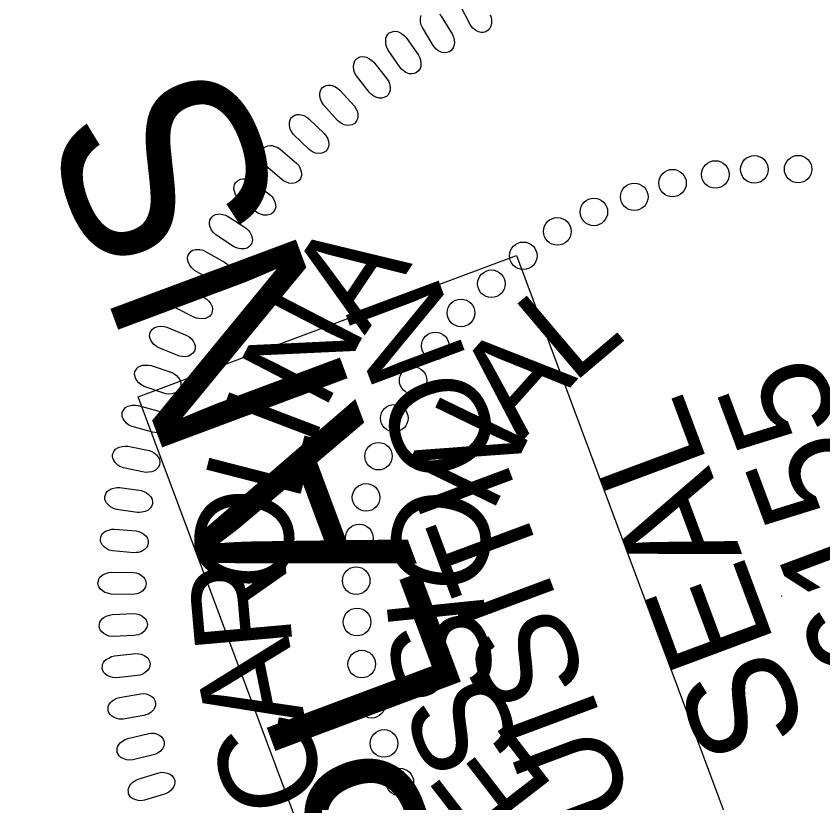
# Model space of a CAD drawing. Extents: x 477774 to 479389, y 493760 to 495720.
# Drawn here: x 477869.32 to 477916.27, y 495305.3 to 495351.06 of the extents above; entities that cross this region are included whole.
import ezdxf

# ---------------------------------------------------------------- set-up
doc = ezdxf.new("R2010")
doc.units = 0
for name, color, linetype in [('Sheet PE Seal Cell', 7, 'Continuous'), ('Sheet Plan CELL', 7, 'Continuous'), ('Sheet Sticker Incomplete CELL', 7, 'Continuous')]:
    doc.layers.add(name, color=color, linetype=linetype)

msp = doc.modelspace()

# ---------------------------------------------------------------- linework, layer by layer
at = {"layer": 'Sheet PE Seal Cell'}
msp.add_line((477913.867, 495317.32), (477913.91, 495317.336), dxfattribs=at)
for points in [[(477896.901, 495351.142), (477896.96, 495350.982), (477896.985, 495350.837), (477896.979, 495350.655), (477896.945, 495350.479), (477896.896, 495350.363), (477896.785, 495350.237), (477896.661, 495350.15), (477896.51, 495350.116), (477896.395, 495350.112), (477896.236, 495350.141), (477896.051, 495350.236), (477895.908, 495350.364), (477895.822, 495350.465), (477895.748, 495350.572), (477895.179, 495351.659)], [(477893.957, 495351.183), (477894.059, 495351.058), (477894.717, 495349.988), (477894.786, 495349.831), (477894.819, 495349.689), (477894.826, 495349.506), (477894.802, 495349.328), (477894.761, 495349.21), (477894.657, 495349.076), (477894.54, 495348.982), (477894.392, 495348.939), (477894.276, 495348.927), (477894.116, 495348.946), (477893.926, 495349.03), (477893.774, 495349.148), (477893.682, 495349.244), (477893.602, 495349.347), (477892.966, 495350.395), (477892.884, 495350.602), (477892.856, 495350.749), (477892.864, 495350.952), (477892.89, 495351.096)]]:
    msp.add_lwpolyline(points, dxfattribs=at)
for points in [[(477891.668, 495348.081), (477890.968, 495349.088), (477890.873, 495349.288), (477890.836, 495349.433), (477890.831, 495349.637), (477890.848, 495349.782), (477890.895, 495349.911), (477890.958, 495350.004), (477891.038, 495350.084), (477891.142, 495350.133), (477891.257, 495350.176), (477891.376, 495350.187), (477891.52, 495350.165), (477891.615, 495350.133), (477891.755, 495350.049), (477891.907, 495349.936), (477892.017, 495349.818), (477892.74, 495348.791), (477892.819, 495348.639), (477892.862, 495348.499), (477892.88, 495348.316), (477892.868, 495348.138), (477892.833, 495348.017), (477892.739, 495347.878), (477892.627, 495347.776), (477892.482, 495347.724), (477892.368, 495347.705), (477892.206, 495347.714), (477892.012, 495347.784), (477891.854, 495347.894), (477891.755, 495347.983)], [(477889.893, 495346.623), (477889.13, 495347.584), (477889.023, 495347.779), (477888.977, 495347.921), (477888.96, 495348.123), (477888.967, 495348.27), (477889.006, 495348.402), (477889.062, 495348.498), (477889.138, 495348.583), (477889.238, 495348.637), (477889.351, 495348.688), (477889.469, 495348.706), (477889.614, 495348.693), (477889.71, 495348.669), (477889.857, 495348.593), (477890.014, 495348.49), (477890.132, 495348.379), (477890.919, 495347.399), (477891.006, 495347.253), (477891.058, 495347.115), (477891.087, 495346.935), (477891.086, 495346.756), (477891.06, 495346.632), (477890.974, 495346.488), (477890.869, 495346.38), (477890.727, 495346.318), (477890.615, 495346.292), (477890.453, 495346.291), (477890.254, 495346.349), (477890.089, 495346.448), (477889.985, 495346.531)], [(477888.031, 495344.995), (477887.209, 495345.906), (477887.09, 495346.094), (477887.035, 495346.232), (477887.005, 495346.433), (477887.004, 495346.58), (477887.034, 495346.714), (477887.084, 495346.814), (477887.154, 495346.904), (477887.251, 495346.964), (477887.36, 495347.022), (477887.477, 495347.048), (477887.622, 495347.043), (477887.72, 495347.025), (477887.87, 495346.959), (477888.035, 495346.865), (477888.158, 495346.762), (477889.006, 495345.833), (477889.102, 495345.693), (477889.163, 495345.559), (477889.203, 495345.38), (477889.213, 495345.202), (477889.194, 495345.077), (477889.118, 495344.927), (477889.02, 495344.813), (477888.883, 495344.742), (477888.771, 495344.709), (477888.61, 495344.698), (477888.408, 495344.744), (477888.237, 495344.832), (477888.129, 495344.909)], [(477886.349, 495343.321), (477885.471, 495344.179), (477885.341, 495344.359), (477885.277, 495344.494), (477885.234, 495344.693), (477885.224, 495344.839), (477885.245, 495344.975), (477885.29, 495345.077), (477885.354, 495345.172), (477885.447, 495345.238), (477885.552, 495345.302), (477885.667, 495345.336), (477885.812, 495345.341), (477885.911, 495345.328), (477886.065, 495345.271), (477886.235, 495345.188), (477886.365, 495345.093), (477887.269, 495344.22), (477887.374, 495344.085), (477887.443, 495343.955), (477887.494, 495343.78), (477887.515, 495343.602), (477887.505, 495343.477), (477887.438, 495343.322), (477887.347, 495343.202), (477887.215, 495343.123), (477887.105, 495343.083), (477886.945, 495343.061), (477886.741, 495343.095), (477886.565, 495343.172), (477886.452, 495343.242)], [(477884.784, 495341.555), (477883.855, 495342.356), (477883.713, 495342.528), (477883.641, 495342.658), (477883.586, 495342.854), (477883.566, 495342.999), (477883.58, 495343.136), (477883.618, 495343.242), (477883.675, 495343.34), (477883.764, 495343.411), (477883.865, 495343.482), (477883.978, 495343.523), (477884.122, 495343.537), (477884.221, 495343.53), (477884.379, 495343.484), (477884.554, 495343.411), (477884.689, 495343.325), (477885.646, 495342.51), (477885.76, 495342.382), (477885.837, 495342.257), (477885.898, 495342.085), (477885.931, 495341.909), (477885.929, 495341.783), (477885.871, 495341.625), (477885.789, 495341.499), (477885.661, 495341.412), (477885.555, 495341.365), (477885.396, 495341.334), (477885.19, 495341.354), (477885.01, 495341.42), (477884.892, 495341.482)], [(477883.305, 495339.657), (477882.327, 495340.398), (477882.175, 495340.561), (477882.095, 495340.686), (477882.027, 495340.878), (477881.998, 495341.022), (477882.003, 495341.159), (477882.034, 495341.267), (477882.086, 495341.368), (477882.169, 495341.446), (477882.266, 495341.523), (477882.376, 495341.57), (477882.52, 495341.593), (477882.619, 495341.593), (477882.779, 495341.556), (477882.958, 495341.495), (477883.099, 495341.417), (477884.105, 495340.664), (477884.226, 495340.544), (477884.31, 495340.424), (477884.384, 495340.256), (477884.427, 495340.082), (477884.432, 495339.956), (477884.385, 495339.795), (477884.311, 495339.664), (477884.189, 495339.569), (477884.086, 495339.516), (477883.929, 495339.474), (477883.722, 495339.481), (477883.538, 495339.536), (477883.417, 495339.591)], [(477881.971, 495337.664), (477880.949, 495338.343), (477880.787, 495338.495), (477880.699, 495338.615), (477880.62, 495338.803), (477880.583, 495338.945), (477880.578, 495339.082), (477880.602, 495339.191), (477880.648, 495339.296), (477880.727, 495339.378), (477880.817, 495339.461), (477880.925, 495339.516), (477881.066, 495339.547), (477881.166, 495339.553), (477881.328, 495339.527), (477881.51, 495339.477), (477881.656, 495339.408), (477882.707, 495338.72), (477882.835, 495338.607), (477882.928, 495338.492), (477883.011, 495338.33), (477883.065, 495338.159), (477883.078, 495338.034), (477883.041, 495337.87), (477882.975, 495337.734), (477882.859, 495337.632), (477882.76, 495337.573), (477882.606, 495337.521), (477882.399, 495337.515), (477882.212, 495337.558), (477882.087, 495337.606)], [(477880.775, 495335.659), (477879.712, 495336.271), (477879.54, 495336.414), (477879.445, 495336.529), (477879.355, 495336.71), (477879.308, 495336.85), (477879.295, 495336.986), (477879.313, 495337.097), (477879.351, 495337.204), (477879.425, 495337.291), (477879.51, 495337.38), (477879.614, 495337.441), (477879.753, 495337.482), (477879.852, 495337.494), (477880.015, 495337.477), (477880.2, 495337.439), (477880.35, 495337.379), (477881.442, 495336.758), (477881.578, 495336.654), (477881.677, 495336.546), (477881.77, 495336.388), (477881.835, 495336.221), (477881.856, 495336.097), (477881.83, 495335.931), (477881.772, 495335.792), (477881.663, 495335.683), (477881.567, 495335.617), (477881.418, 495335.556), (477881.211, 495335.537), (477881.022, 495335.569), (477880.894, 495335.608)], [(477879.702, 495333.538), (477878.603, 495334.083), (477878.424, 495334.214), (477878.321, 495334.322), (477878.219, 495334.498), (477878.164, 495334.634), (477878.142, 495334.769), (477878.153, 495334.881), (477878.184, 495334.991), (477878.253, 495335.082), (477878.332, 495335.176), (477878.432, 495335.244), (477878.568, 495335.293), (477878.666, 495335.311), (477878.83, 495335.305), (477879.017, 495335.279), (477879.171, 495335.228), (477880.3, 495334.677), (477880.442, 495334.582), (477880.547, 495334.48), (477880.65, 495334.329), (477880.725, 495334.166), (477880.754, 495334.043), (477880.738, 495333.876), (477880.689, 495333.733), (477880.588, 495333.617), (477880.496, 495333.546), (477880.35, 495333.476), (477880.145, 495333.444), (477879.954, 495333.464), (477879.825, 495333.494)], [(477878.726, 495331.312), (477877.594, 495331.786), (477877.406, 495331.905), (477877.298, 495332.008), (477877.185, 495332.177), (477877.121, 495332.309), (477877.091, 495332.443), (477877.095, 495332.555), (477877.12, 495332.666), (477877.181, 495332.762), (477877.255, 495332.86), (477877.351, 495332.934), (477877.484, 495332.992), (477877.581, 495333.016), (477877.744, 495333.02), (477877.933, 495333.006), (477878.088, 495332.965), (477879.25, 495332.486), (477879.398, 495332.4), (477879.509, 495332.304), (477879.622, 495332.16), (477879.707, 495332.003), (477879.743, 495331.882), (477879.738, 495331.714), (477879.698, 495331.568), (477879.604, 495331.446), (477879.517, 495331.369), (477879.376, 495331.29), (477879.174, 495331.246), (477878.982, 495331.253), (477878.851, 495331.276)], [(477877.927, 495329.123), (477876.768, 495329.525), (477876.573, 495329.632), (477876.458, 495329.727), (477876.335, 495329.889), (477876.263, 495330.017), (477876.225, 495330.149), (477876.221, 495330.26), (477876.24, 495330.374), (477876.294, 495330.472), (477876.362, 495330.576), (477876.453, 495330.655), (477876.582, 495330.721), (477876.677, 495330.752), (477876.84, 495330.765), (477877.029, 495330.764), (477877.187, 495330.733), (477878.377, 495330.327), (477878.53, 495330.251), (477878.647, 495330.162), (477878.768, 495330.025), (477878.864, 495329.873), (477878.907, 495329.755), (477878.912, 495329.588), (477878.881, 495329.44), (477878.795, 495329.312), (477878.714, 495329.229), (477878.578, 495329.142), (477878.379, 495329.085), (477878.186, 495329.08), (477878.054, 495329.095)], [(477877.263, 495326.852), (477876.081, 495327.181), (477875.879, 495327.276), (477875.759, 495327.364), (477875.626, 495327.517), (477875.546, 495327.64), (477875.499, 495327.769), (477875.489, 495327.882), (477875.499, 495327.995), (477875.549, 495328.097), (477875.61, 495328.204), (477875.695, 495328.289), (477875.82, 495328.364), (477875.912, 495328.4), (477876.075, 495328.425), (477876.263, 495328.434), (477876.423, 495328.413), (477877.636, 495328.083), (477877.793, 495328.016), (477877.916, 495327.935), (477878.045, 495327.806), (477878.15, 495327.661), (477878.201, 495327.545), (477878.216, 495327.378), (477878.195, 495327.229), (477878.117, 495327.096), (477878.041, 495327.008), (477877.911, 495326.912), (477877.715, 495326.843), (477877.524, 495326.826), (477877.391, 495326.832)], [(477876.769, 495324.534), (477875.569, 495324.788), (477875.362, 495324.87), (477875.237, 495324.95), (477875.094, 495325.094), (477875.006, 495325.212), (477874.952, 495325.339), (477874.934, 495325.449), (477874.938, 495325.563), (477874.981, 495325.669), (477875.035, 495325.779), (477875.115, 495325.869), (477875.234, 495325.951), (477875.325, 495325.993), (477875.485, 495326.028), (477875.673, 495326.049), (477875.834, 495326.038), (477877.065, 495325.785), (477877.226, 495325.728), (477877.353, 495325.655), (477877.491, 495325.535), (477877.604, 495325.396), (477877.663, 495325.285), (477877.689, 495325.118), (477877.676, 495324.968), (477877.607, 495324.831), (477877.536, 495324.738), (477877.412, 495324.634), (477877.222, 495324.553), (477877.032, 495324.524), (477876.899, 495324.522)], [(477876.379, 495322.191), (477875.165, 495322.369), (477874.954, 495322.438), (477874.823, 495322.51), (477874.672, 495322.646), (477874.577, 495322.758), (477874.514, 495322.881), (477874.49, 495322.99), (477874.487, 495323.103), (477874.523, 495323.211), (477874.57, 495323.325), (477874.644, 495323.42), (477874.758, 495323.509), (477874.846, 495323.557), (477875.003, 495323.602), (477875.19, 495323.635), (477875.351, 495323.634), (477876.595, 495323.459), (477876.759, 495323.412), (477876.891, 495323.347), (477877.036, 495323.236), (477877.158, 495323.104), (477877.223, 495322.997), (477877.259, 495322.832), (477877.257, 495322.682), (477877.196, 495322.539), (477877.131, 495322.443), (477877.014, 495322.332), (477876.829, 495322.238), (477876.642, 495322.198), (477876.509, 495322.187)], [(477876.17, 495319.846), (477874.948, 495319.948), (477874.732, 495320.003), (477874.598, 495320.067), (477874.438, 495320.193), (477874.336, 495320.298), (477874.266, 495320.417), (477874.235, 495320.525), (477874.225, 495320.638), (477874.254, 495320.748), (477874.293, 495320.865), (477874.362, 495320.964), (477874.47, 495321.06), (477874.554, 495321.113), (477874.709, 495321.168), (477874.893, 495321.212), (477875.054, 495321.222), (477876.307, 495321.125), (477876.474, 495321.089), (477876.609, 495321.032), (477876.761, 495320.93), (477876.891, 495320.806), (477876.962, 495320.703), (477877.009, 495320.541), (477877.016, 495320.391), (477876.964, 495320.246), (477876.906, 495320.145), (477876.796, 495320.027), (477876.617, 495319.922), (477876.433, 495319.869), (477876.301, 495319.851)], [(477876.079, 495317.42), (477874.853, 495317.444), (477874.634, 495317.486), (477874.495, 495317.541), (477874.328, 495317.657), (477874.22, 495317.756), (477874.143, 495317.87), (477874.105, 495317.975), (477874.087, 495318.088), (477874.11, 495318.199), (477874.142, 495318.318), (477874.204, 495318.422), (477874.306, 495318.525), (477874.387, 495318.583), (477874.537, 495318.647), (477874.718, 495318.704), (477874.878, 495318.723), (477876.135, 495318.705), (477876.304, 495318.678), (477876.443, 495318.631), (477876.6, 495318.538), (477876.738, 495318.424), (477876.815, 495318.325), (477876.872, 495318.166), (477876.889, 495318.016), (477876.846, 495317.868), (477876.794, 495317.764), (477876.692, 495317.639), (477876.52, 495317.523), (477876.339, 495317.459), (477876.209, 495317.432)], [(477876.189, 495315.024), (477874.963, 495314.971), (477874.742, 495314.999), (477874.601, 495315.046), (477874.426, 495315.15), (477874.313, 495315.243), (477874.228, 495315.351), (477874.184, 495315.454), (477874.159, 495315.565), (477874.175, 495315.678), (477874.2, 495315.799), (477874.255, 495315.907), (477874.35, 495316.015), (477874.427, 495316.078), (477874.573, 495316.152), (477874.75, 495316.219), (477874.909, 495316.248), (477876.164, 495316.309), (477876.334, 495316.295), (477876.476, 495316.255), (477876.639, 495316.173), (477876.783, 495316.066), (477876.867, 495315.973), (477876.934, 495315.819), (477876.96, 495315.67), (477876.926, 495315.519), (477876.881, 495315.413), (477876.787, 495315.281), (477876.623, 495315.155), (477876.446, 495315.079), (477876.318, 495315.044)], [(477876.393, 495312.698), (477875.173, 495312.569), (477874.952, 495312.583), (477874.806, 495312.62), (477874.626, 495312.714), (477874.507, 495312.799), (477874.416, 495312.902), (477874.365, 495313.002), (477874.333, 495313.111), (477874.341, 495313.225), (477874.358, 495313.347), (477874.407, 495313.457), (477874.495, 495313.572), (477874.568, 495313.64), (477874.71, 495313.722), (477874.882, 495313.801), (477875.039, 495313.841), (477876.288, 495313.98), (477876.458, 495313.975), (477876.602, 495313.945), (477876.77, 495313.873), (477876.921, 495313.776), (477877.01, 495313.688), (477877.086, 495313.538), (477877.122, 495313.392), (477877.097, 495313.239), (477877.059, 495313.13), (477876.974, 495312.993), (477876.818, 495312.856), (477876.646, 495312.77), (477876.521, 495312.727)], [(477876.755, 495310.373), (477875.546, 495310.167), (477875.323, 495310.167), (477875.177, 495310.196), (477874.991, 495310.278), (477874.867, 495310.355), (477874.77, 495310.452), (477874.713, 495310.548), (477874.674, 495310.656), (477874.675, 495310.77), (477874.684, 495310.893), (477874.726, 495311.006), (477874.807, 495311.126), (477874.875, 495311.198), (477875.011, 495311.289), (477875.178, 495311.379), (477875.332, 495311.428), (477876.57, 495311.646), (477876.74, 495311.651), (477876.885, 495311.631), (477877.058, 495311.569), (477877.214, 495311.482), (477877.309, 495311.4), (477877.394, 495311.255), (477877.439, 495311.111), (477877.425, 495310.957), (477877.393, 495310.846), (477877.316, 495310.704), (477877.169, 495310.557), (477877.004, 495310.461), (477876.881, 495310.409)], [(477877.305, 495308.081), (477876.111, 495307.8), (477875.889, 495307.786), (477875.741, 495307.805), (477875.55, 495307.875), (477875.421, 495307.945), (477875.318, 495308.036), (477875.255, 495308.128), (477875.21, 495308.233), (477875.204, 495308.347), (477875.205, 495308.469), (477875.24, 495308.585), (477875.313, 495308.71), (477875.377, 495308.786), (477875.507, 495308.887), (477875.668, 495308.985), (477875.818, 495309.044), (477877.04, 495309.339), (477877.21, 495309.356), (477877.356, 495309.345), (477877.532, 495309.294), (477877.693, 495309.217), (477877.793, 495309.141), (477877.887, 495309.001), (477877.941, 495308.861), (477877.937, 495308.706), (477877.912, 495308.593), (477877.844, 495308.446), (477877.707, 495308.29), (477877.547, 495308.184), (477877.427, 495308.125)], [(477877.967, 495305.807), (477876.793, 495305.451), (477876.572, 495305.423), (477876.424, 495305.433), (477876.228, 495305.491), (477876.096, 495305.552), (477875.986, 495305.636), (477875.918, 495305.725), (477875.867, 495305.827), (477875.854, 495305.939), (477875.847, 495306.063), (477875.874, 495306.18), (477875.939, 495306.309), (477875.998, 495306.389), (477876.122, 495306.498), (477876.276, 495306.606), (477876.422, 495306.674), (477877.623, 495307.045), (477877.792, 495307.074), (477877.938, 495307.071), (477878.117, 495307.031), (477878.283, 495306.964), (477878.388, 495306.895), (477878.491, 495306.762), (477878.553, 495306.624), (477878.558, 495306.47), (477878.54, 495306.355), (477878.482, 495306.204), (477878.355, 495306.041), (477878.202, 495305.925), (477878.086, 495305.858)]]:
    msp.add_lwpolyline(points, close=True, dxfattribs=at)
for centre in [(477912.285, 495342.146), (477914.831, 495342.161), (477910.014, 495341.852), (477907.523, 495341.348), (477905.298, 495340.549), (477902.947, 495339.672), (477900.819, 495338.539), (477898.839, 495337.121), (477896.98, 495335.493), (477895.213, 495333.795), (477893.717, 495331.878), (477892.426, 495329.867), (477891.331, 495327.674), (477890.412, 495325.462), (477889.689, 495323.067), (477889.293, 495320.71), (477889.115, 495318.222), (477889.162, 495315.817), (477889.436, 495313.37), (477890.01, 495311.034), (477890.732, 495308.754), (477891.656, 495306.507)]:
    msp.add_circle(centre, 0.801, dxfattribs=at)
at = {"layer": 'Sheet Sticker Incomplete CELL'}
msp.add_lwpolyline([(477949.848, 495199.411), (477927.831, 495191.193), (477876.425, 495328.912), (477898.442, 495337.13)], close=True, dxfattribs=at)

# ---------------------------------------------------------------- texts
at = {"layer": 'Sheet PE Seal Cell'}
for s, height, rotation, p in [('A', 5.669, 56.1418, (477889.601, 495332.461)), ('N', 5.669, 62.6312, (477887.22, 495328.029)), ('L', 5.669, 40.2998, (477901.692, 495329.618)), ('A', 5.669, 48.2396, (477898.692, 495326.231)), ('46155', 6.2363, 110.4503, (477923.857, 495309.958)), ('I', 5.669, 69.1205, (477886.521, 495325.841)), ('N', 5.669, 64.1192, (477896.973, 495322.028)), ('SEAL', 6.2363, 110.4503, (477915.467, 495309.333)), ('L', 5.669, 75.6099, (477885.727, 495322.67)), ('O', 5.669, 82.0992, (477885.01, 495317.351)), ('O', 5.669, 79.9988, (477896.322, 495317.182)), ('R', 5.669, 95.0779, (477885.431, 495314.354)), ('I', 5.669, 95.8784, (477896.687, 495315.714)), ('S', 5.669, 103.8182, (477897.424, 495311.932)), ('A', 5.669, 101.5673, (477886.158, 495310.135)), ('S', 5.669, 111.758, (477898.869, 495308.351)), ('C', 5.669, 108.0567, (477887.563, 495305.776)), ('E', 5.669, 127.6376, (477900.736, 495306.094))]:
    msp.add_text(s, height=height, rotation=rotation, dxfattribs=at).set_placement(p)
at = {"layer": 'Sheet Plan CELL'}
msp.add_text('ENGINEER', height=5.0001, rotation=110.469, dxfattribs=at).set_placement((477873.753, 495285.992))
at = {"layer": 'Sheet Sticker Incomplete CELL'}
for s, height, p in [('INCOMPLETE PLANS', 11.52, (477935.756, 495203.705)), ('DO NOT USE FOR R/W ACQUISITION', 5.76, (477941.131, 495209.18))]:
    msp.add_text(s, height=height, rotation=110.469, dxfattribs=at).set_placement(p)

doc.saveas('drawing.dxf')
